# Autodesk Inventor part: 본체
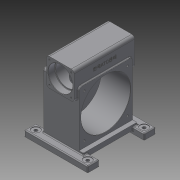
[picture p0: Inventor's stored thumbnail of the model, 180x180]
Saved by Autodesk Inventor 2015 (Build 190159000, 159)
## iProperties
Created: 2025-06
Part Number: 본체
Material: 일반
Document SubType Name: Modeling
Designer: User
Density: 1 g/cm^3
Appearance: 기본값
Author: User
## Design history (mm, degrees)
sketch "스케치2"
  geometry: L1 (93, -103)-(-93, -103); L2 (-93, -103)-(-93, 103); L3 (-93, 103)-(93, 103); L4 (93, 103)-(93, -103); L5 (93, -103)-(-93, 103); L6 (-93, -103)-(93, 103); 1 further point
  constraints: 12 end point, 2 midpoint, 2 parallel, 1 horizontal, 1 perpendicular
  dimensions: "d0" = 186 distance of L2.end L3.end; "d1" = 206 distance of L1.end L2.end
extrude "돌출1" new body sketch "스케치2" distance "d2" = 55; taper "d3" = 0 deg; dims "d48" = 70, "d49" = 0
sketch "스케치4"
  geometry: L1 (46, 158)-(-50, 158); L2 (-50, 158)-(-50, 62); L3 (-50, 62)-(46, 62); L4 (46, 62)-(46, 158); L5 (46, 158)-(-50, 62); L6 (-50, 158)-(46, 62); L7 (70, 103)-(70, -103) reference; L8 (70, -103)-(-55, -103) reference; L9 (-55, -103)-(-55, 103) reference; L10 (-55, 103)-(70, 103) reference; 2 further points
  constraints: 12 end point, 2 midpoint, 2 parallel, 1 horizontal, 1 perpendicular
  dimensions: "d6" = 96 distance of L3.end L2.end; "d7" = 96 distance of L2.end L1.end; "d9" = 5 distance between parallel lines of L9 L2; "d72" = 261 distance between parallel lines of L8 L1
extrude "돌출2" join sketch "스케치4" stored distance "d10" = 210; taper "d11" = 0 deg
sketch "스케치9"
  geometry: L1 (50, 158)-(-46, 158) reference; L2 (50, 62)-(50, 158) reference; C1 r 42.5 at (2, 110); 3 further points
  constraints: 2 midpoint, 1 centre point, 1 horizontal alignment, 1 vertical alignment
  dimensions: "d21" = 85 diameter of C1
extrude "돌출6" cut sketch "스케치9" distance "d22" = 23; taper "d23" = 0 deg
sketch "스케치10"
  geometry: C1 r 42.5 at (0, 0) reference; C2 r 38.5 at (0, 0); 1 further point
  constraints: 1 centre point, 1 coincident
  dimensions: "d24" = 77 diameter of C2
extrude "돌출7" cut sketch "스케치10" stored distance "d25" = 0; taper "d26" = 0 deg
sketch "스케치11"
  geometry: C1 r 38.5 at (2, -110) reference; C2 r 42.5 at (2, -110); 1 further point
  constraints: 1 centre point, 1 coincident
  dimensions: "d27" = 85 diameter of C2
extrude "돌출8" cut sketch "스케치11" distance "d28" = 23; taper "d29" = 0 deg
node "작업 평면3"
sketch "스케치16"
  geometry: L1 (165, -211)-(-55, -211); L2 (-55, -211)-(-55, -171); L3 (-55, -171)-(165, -171); L4 (165, -171)-(165, -211); 2 further points
  constraints: 8 end point, 2 parallel, 1 horizontal, 1 midpoint, 1 perpendicular, 1 vertical alignment
  dimensions: "d58" = 40 distance between parallel lines of L3 L1; "d59" = 220 distance between parallel lines of L4 L2; "d60" = 118 distance of point (55, -93) point (55, -211)
extrude "돌출11" join sketch "스케치16" distance "d61" = 20; taper "d62" = 0 deg
sketch "스케치20"
  geometry: L1 (0, -171)-(55, -171) reference; L2 (55, -171)-(55, -211) reference; L3 (55, -211)-(-165, -211) reference; L4 (-165, -211)-(-165, -171) reference; L5 (-165, -171)-(-125, -171) reference; L6 (-125, -186)-(-125, -171) reference; L7 (0, -186)-(-125, -186) reference; L8 (0, -171)-(0, -186) reference; L9 (0, 0)-(0, -171) reference; L10 (-125, 0)-(0, 0) reference; L11 (-125, -171)-(-125, 0) reference; 2 further points
  dimensions: "d63" = 98 vertical distance of point (-55, -93) point (35, -191); "d64" = 90 horizontal distance of point (-55, -93) point (35, -191)
hole "구멍2" sketch "스케치20" at (35, -191) diameter "d65" = 11; stored, may be unused: countersink angle "d69" = 90 deg, drill point angle "d71" = 118 deg; dims "d66" = 6, "d67" = 28, "d68" = 2, "d70" = 8
sketch "스케치25"
  geometry: L1 (0, 0)-(0, 156) reference; L2 (0, -15)-(-15, -15); L3 (-15, -15)-(-15, 171); L4 (-15, 171)-(0, 171); L5 (0, 171)-(0, -15); 3 further points
  constraints: 8 end point, 2 midpoint, 2 parallel, 1 coincident, 1 horizontal, 1 horizontal alignment, 1 perpendicular
  dimensions: "d74" = 15 distance of L3.end L4.end; "d75" = 186 distance between parallel lines of L2 L4
extrude "돌출12" join sketch "스케치25" distance "d76" = 17; taper "d77" = 0 deg
sketch "스케치26"
  geometry: L1 (113, -118)-(113, -78) reference; C1 r 86 at (-10, 0); 1 further point
  constraints: 1 centre point, 1 horizontal alignment
  dimensions: "d78" = 123 distance from line of L1 C1.centre; "d79" = 172 diameter of C1
extrude "돌출13" cut sketch "스케치26" distance "d80" = 102; taper "d81" = 0 deg
sketch "스케치28"
  geometry: C1 r 86 at (0, 0) reference; C2 r 31 at (0, 0); 1 further point
  constraints: 1 centre point, 1 coincident
  dimensions: "d82" = 62 diameter of C2
extrude "돌출14" cut sketch "스케치28" distance "d83" = 16; taper "d84" = 0 deg
sketch "스케치29"
  geometry: C1 r 31 at (0, 0) reference; C2 r 27 at (0, 0); 1 further point
  constraints: 1 centre point, 1 coincident
  dimensions: "d85" = 54 diameter of C2
extrude "돌출15" cut sketch "스케치29" distance "d86" = 3; taper "d87" = 0 deg
fillet "모깎기3" dims "d90" = 10
fillet "모깎기4" dims "d91" = 10
fillet "모깎기5" dims "d92" = 3
sketch "스케치30"
  geometry: A1 r 10 centre (-36, 72) between (-46, 72) and (-36, 62) reference; A2 r 10 centre (40, 72) between (40, 62) and (50, 72) reference; A3 r 10 centre (40, 148) between (50, 148) and (40, 158) reference; A4 r 10 centre (-36, 148) between (-36, 158) and (-46, 148) reference; 1 further point
hole "구멍3" sketch "스케치30" at (-36, 148), (40, 148), (40, 72), (-36, 72) diameter "d93" = 4.917; stored, may be unused: countersink angle "d97" = 90 deg, drill point angle "d99" = 118 deg; dims "d94" = 12, "d95" = 28, "d96" = 2, "d98" = 14
sketch "스케치32"
  geometry: L1 (65, 75)-(-85, 75); L2 (-85, 75)-(-85, -75); L3 (-85, -75)-(65, -75); L4 (65, -75)-(65, 75); L5 (65, 75)-(-85, -75); L6 (-85, 75)-(65, -75); C1 r 86 at (-10, 0) reference; 2 further points
  constraints: 12 end point, 3 midpoint, 2 parallel, 1 coincident, 1 horizontal, 1 perpendicular
  dimensions: "d113" = 150 distance of L3.end L2.end; "d114" = 150 distance of L2.end L1.end
hole "구멍5" sketch "스케치32" at (-85, -75), (-85, 75), (65, 75), (65, -75) diameter "d115" = 6.647; stored, may be unused: countersink angle "d119" = 90 deg, drill point angle "d121" = 118 deg; dims "d116" = 16, "d117" = 28, "d118" = 2, "d120" = 18
fillet "모깎기6" dims "d122" = 3
fillet "모깎기7" dims "d123" = 3
fillet "모깎기8" dims "d124" = 3
fillet "모깎기9" dims "d125" = 3
fillet "모깎기10" dims "d126" = 3
sketch "스케치33"
  geometry: L1 (-10, 210)-(-10, 0) reference; 2 further points
  constraints: 1 other
  dimensions: "d127" = 30 distance from line of L1 point (20, 106.005)
feature "엠보싱1" sketch "스케치33" dims "d128" = 0.5, "d129" = 0
fillet "모깎기11" dims "d130" = 1
chamfer "모따기1" distance "d131" = 1; stored, may be unused: second distance "d132" = 2, angle "d133" = 45 deg
fillet "모깎기12" dims "d134" = 3
fillet "모깎기13" dims "d135" = 3
chamfer "모따기2" distance "d136" = 1; stored, may be unused: second distance "d137" = 2, angle "d138" = 45 deg
fillet "모깎기14" dims "d139" = 1.1
node "솔리드1"
mirror "대칭3"
mirror "대칭4"
mirror "대칭5"
node "절단 모서리 투영1"
node "절단 모서리 투영4"
